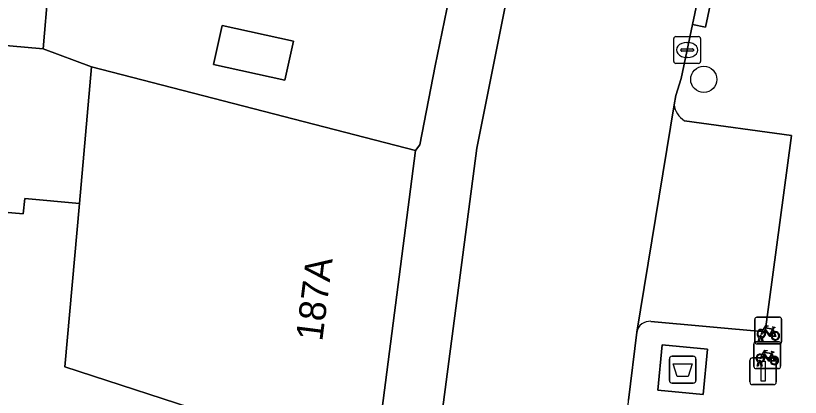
# Model space of a CAD drawing. Extents: x 161248 to 161848, y 384871 to 385383.
# Drawn here: x 161674.85 to 161704.18, y 384990.69 to 385004.94 of the extents above; entities that cross this region are included whole.
import ezdxf

# ---------------------------------------------------------------- set-up
doc = ezdxf.new("R2010")
doc.units = 0
for name, color, linetype in [('IMGEO_Afval_apart_plaats', 7, 'Continuous'), ('IMGEO_Boom', 7, 'Continuous'), ('IMGEO_Erf', 7, 'Continuous'), ('IMGEO_Fietsenrek', 7, 'Continuous'), ('IMGEO_Kolk', 7, 'Continuous'), ('IMGEO_Lichtmast', 7, 'Continuous'), ('IMGEO_Pand', 7, 'Continuous'), ('IMGEO_Pand_nummerreeks', 7, 'Continuous'), ('IMGEO_Parkeervlak_open', 7, 'Continuous'), ('IMGEO_Rijbaan_lokaal_open', 7, 'Continuous'), ('IMGEO_Voetpad_gesloten', 7, 'Continuous'), ('IMGEO_Voetpad_open', 7, 'Continuous')]:
    doc.layers.add(name, color=color, linetype=linetype)

msp = doc.modelspace()

# ---------------------------------------------------------------- linework, layer by layer
at = {"layer": 'IMGEO_Afval_apart_plaats'}
for p, q in [((161699.392, 384992.22), (161700.182, 384992.22)), ((161700.182, 384992.22), (161699.392, 384992.22)), ((161699.292, 384991.32), (161699.292, 384992.12)), ((161699.292, 384992.12), (161699.292, 384991.32)), ((161700.282, 384992.12), (161700.282, 384991.32)), ((161700.282, 384991.32), (161700.282, 384992.12)), ((161700.182, 384991.22), (161699.392, 384991.22)), ((161699.392, 384991.22), (161700.182, 384991.22))]:
    msp.add_line(p, q, dxfattribs=at)
msp.add_lwpolyline([(161699.435, 384991.934), (161700.139, 384991.934), (161699.99, 384991.464), (161699.584, 384991.464), (161699.435, 384991.934)], dxfattribs=at)
for centre, start, end in [((161699.392, 384992.12), 90, 180), ((161699.392, 384992.12), 90, 180), ((161700.182, 384992.12), 0, 90), ((161700.182, 384992.12), 360, 90), ((161699.392, 384991.32), 180, 270), ((161699.392, 384991.32), 180, 270), ((161700.182, 384991.32), 270, 0), ((161700.182, 384991.32), 270, 0)]:
    msp.add_arc(centre, 0.1, start, end, dxfattribs=at)
at = {"layer": 'IMGEO_Boom'}
msp.add_circle((161700.575, 385002.565), 0.489, dxfattribs=at)
at = {"layer": 'IMGEO_Erf'}
for points in [[(161676.071, 385005.916), (161675.876, 385003.712), (161677.685, 385003.029), (161689.793, 384999.91), (161689.963, 385000.114), (161690.54, 385003.076), (161691.142, 385006.05)], [(161687.042, 384959.42), (161687.564, 384974.827), (161681.278, 384975.098), (161680.356, 384975.133), (161680.242, 384972.094), (161674.921, 384972.295), (161675.036, 384975.334), (161676.32, 384975.285), (161676.539, 384981.075), (161681.479, 384980.93), (161682.094, 384980.912), (161682.436, 384989.956), (161676.695, 384991.828), (161677.235, 384997.933), (161675.189, 384998.114), (161675.139, 384997.544), (161670.463, 384997.957)]]:
    msp.add_lwpolyline(points, dxfattribs=at)
msp.add_lwpolyline([(161685.233, 385003.995), (161684.91, 385002.53), (161682.251, 385003.116), (161682.574, 385004.58)], close=True, dxfattribs=at)
at = {"layer": 'IMGEO_Fietsenrek'}
for p, q in [((161702.485, 384992.757), (161702.485, 384993.598)), ((161702.485, 384993.598), (161702.485, 384992.757)), ((161702.56, 384993.682), (161703.401, 384993.682)), ((161703.401, 384993.682), (161702.56, 384993.682)), ((161703.485, 384993.607), (161703.485, 384992.766)), ((161703.485, 384992.766), (161703.485, 384993.607)), ((161703.172, 384993.231), (161703.208, 384993.136)), ((161702.523, 384992.763), (161703.364, 384992.763)), ((161703.364, 384992.763), (161702.523, 384992.763)), ((161702.612, 384992.766), (161702.651, 384992.926)), ((161702.646, 384992.766), (161702.612, 384992.766)), ((161702.681, 384992.914), (161702.646, 384992.766)), ((161702.723, 384992.938), (161702.722, 384992.942)), ((161702.764, 384992.766), (161702.73, 384992.908)), ((161702.754, 384992.949), (161702.755, 384992.942)), ((161702.762, 384992.912), (161702.797, 384992.766)), ((161702.797, 384992.766), (161702.764, 384992.766)), ((161702.448, 384991.838), (161702.448, 384992.679)), ((161702.448, 384992.679), (161702.448, 384991.838)), ((161703.41, 384992.682), (161702.569, 384992.682)), ((161702.569, 384992.682), (161703.41, 384992.682)), ((161703.448, 384992.688), (161703.448, 384991.847)), ((161703.448, 384991.847), (161703.448, 384992.688)), ((161703.135, 384992.312), (161703.171, 384992.217)), ((161702.575, 384991.847), (161702.614, 384992.007)), ((161702.609, 384991.847), (161702.575, 384991.847)), ((161702.644, 384991.995), (161702.609, 384991.847)), ((161702.686, 384992.019), (161702.685, 384992.023)), ((161702.727, 384991.847), (161702.693, 384991.989)), ((161702.717, 384992.03), (161702.718, 384992.023)), ((161702.725, 384991.993), (161702.76, 384991.847)), ((161702.76, 384991.847), (161702.727, 384991.847)), ((161703.373, 384991.763), (161702.532, 384991.763)), ((161702.532, 384991.763), (161703.373, 384991.763))]:
    msp.add_line(p, q, dxfattribs=at)
for points in [[(161702.798, 384993.208), (161702.893, 384993.372), (161702.979, 384993.358), (161702.981, 384993.349), (161702.925, 384993.338), (161702.898, 384993.293), (161703.154, 384993.252)], [(161703.154, 384993.252), (161703.179, 384993.301), (161703.173, 384993.305), (161703.15, 384993.309), (161703.138, 384993.316), (161703.137, 384993.319), (161703.139, 384993.324), (161703.234, 384993.309), (161703.236, 384993.299), (161703.226, 384993.286), (161703.214, 384993.28), (161703.2, 384993.286), (161703.172, 384993.231)], [(161702.819, 384993.156), (161702.767, 384993.066), (161702.727, 384993.041), (161702.728, 384993.088), (161702.783, 384993.182)], [(161703.094, 384992.964), (161703.044, 384992.964), (161702.853, 384993.215), (161702.834, 384993.183)], [(161703.141, 384993.227), (161702.884, 384993.268), (161702.867, 384993.239), (161703.034, 384993.019), (161703.141, 384993.227)], [(161703.189, 384993.129), (161703.159, 384993.206), (161703.05, 384992.988), (161703.093, 384992.988)], [(161703.123, 384992.988), (161703.243, 384992.987), (161703.199, 384993.101)], [(161703.219, 384993.108), (161703.274, 384992.963), (161703.124, 384992.963)], [(161702.761, 384992.289), (161702.856, 384992.453), (161702.942, 384992.439), (161702.944, 384992.43), (161702.888, 384992.419), (161702.861, 384992.374), (161703.117, 384992.333)], [(161702.782, 384992.237), (161702.73, 384992.147), (161702.69, 384992.122), (161702.691, 384992.169), (161702.746, 384992.263)], [(161703.057, 384992.045), (161703.007, 384992.045), (161702.816, 384992.296), (161702.797, 384992.264)], [(161703.104, 384992.308), (161702.847, 384992.349), (161702.83, 384992.32), (161702.997, 384992.1), (161703.104, 384992.308)], [(161703.152, 384992.21), (161703.122, 384992.287), (161703.013, 384992.069), (161703.056, 384992.069)], [(161703.086, 384992.069), (161703.206, 384992.068), (161703.162, 384992.182)], [(161703.182, 384992.189), (161703.237, 384992.044), (161703.087, 384992.044)], [(161703.117, 384992.333), (161703.142, 384992.382), (161703.136, 384992.386), (161703.113, 384992.39), (161703.101, 384992.397), (161703.1, 384992.4), (161703.102, 384992.405), (161703.197, 384992.39), (161703.199, 384992.38), (161703.189, 384992.367), (161703.177, 384992.361), (161703.163, 384992.367), (161703.135, 384992.312)]]:
    msp.add_lwpolyline(points, dxfattribs=at)
for centre, radius, start, end in [((161702.563, 384993.604), 0.0779, 92.4484, 184.2845), ((161702.563, 384993.604), 0.0779, 92.4484, 184.2845), ((161703.407, 384993.604), 0.0779, 2.4484, 94.2845), ((161703.407, 384993.604), 0.0779, 2.4484, 94.2845), ((161702.725, 384993.067), 0.159, 62.6766, 242.1369), ((161702.725, 384993.067), 0.129, 63.3192, 238.903), ((161702.725, 384993.067), 0.129, 283.6043, 43.4302), ((161702.725, 384993.067), 0.159, 283.5766, 46.6042), ((161703.252, 384992.983), 0.159, 113.3408, 178.3217), ((161703.252, 384992.983), 0.159, 187.0065, 105.7708), ((161703.252, 384992.983), 0.129, 113.923, 177.9556), ((161703.252, 384992.983), 0.129, 188.6715, 104.5883), ((161702.526, 384992.685), 0.0779, 92.4484, 184.2845), ((161702.526, 384992.685), 0.0779, 92.4484, 184.2845), ((161702.563, 384992.76), 0.0779, 182.4484, 274.2845), ((161702.563, 384992.76), 0.0779, 182.4484, 274.2845), ((161702.705, 384992.938), 0.0499, 12.8025, 158.6934), ((161702.725, 384993.067), 0.159, 253.9967, 271.7867), ((161702.705, 384992.938), 0.0174, 12.8025, 163.4502), ((161702.725, 384993.067), 0.129, 253.415, 269.0204), ((161703.37, 384992.685), 0.0779, 2.4484, 94.2845), ((161703.37, 384992.685), 0.0779, 2.4484, 94.2845), ((161703.407, 384992.76), 0.0779, 272.4484, 4.2845), ((161703.407, 384992.76), 0.0779, 272.4484, 4.2845), ((161702.688, 384992.148), 0.159, 62.6766, 242.1369), ((161702.688, 384992.148), 0.129, 63.3192, 238.903), ((161702.688, 384992.148), 0.129, 283.6043, 43.4302), ((161702.688, 384992.148), 0.159, 283.5766, 46.6042), ((161703.215, 384992.064), 0.159, 113.3408, 178.3217), ((161703.215, 384992.064), 0.159, 187.0065, 105.7708), ((161703.215, 384992.064), 0.129, 113.923, 177.9556), ((161703.215, 384992.064), 0.129, 188.6715, 104.5883), ((161702.526, 384991.841), 0.0779, 182.4484, 274.2845), ((161702.526, 384991.841), 0.0779, 182.4484, 274.2845), ((161702.668, 384992.019), 0.0499, 12.8025, 158.6934), ((161702.688, 384992.148), 0.159, 253.9967, 271.7867), ((161702.668, 384992.019), 0.0174, 12.8025, 163.4502), ((161702.688, 384992.148), 0.129, 253.415, 269.0204), ((161703.37, 384991.841), 0.0779, 272.4484, 4.2845), ((161703.37, 384991.841), 0.0779, 272.4484, 4.2845)]:
    msp.add_arc(centre, radius, start, end, dxfattribs=at)
at = {"layer": 'IMGEO_Kolk'}
for p, q in [((161699.53, 385004.164), (161700.382, 385004.164)), ((161699.455, 385003.238), (161699.455, 385004.09)), ((161699.943, 385003.944), (161699.968, 385003.944)), ((161700.456, 385004.09), (161700.456, 385003.238)), ((161699.714, 385003.658), (161699.714, 385003.67)), ((161700.152, 385003.621), (161699.754, 385003.621)), ((161699.757, 385003.707), (161700.155, 385003.707)), ((161700.198, 385003.67), (161700.198, 385003.658)), ((161699.966, 385003.384), (161699.941, 385003.384)), ((161700.382, 385003.164), (161699.53, 385003.164))]:
    msp.add_line(p, q, dxfattribs=at)
for points in [[(161699.53, 385004.164), (161700.382, 385004.164)], [(161699.455, 385003.238), (161699.455, 385004.09)], [(161700.456, 385004.09), (161700.456, 385003.238)], [(161700.382, 385003.164), (161699.53, 385003.164)]]:
    msp.add_lwpolyline(points, dxfattribs=at)
for centre, radius, start, end in [((161699.532, 385004.088), 0.0765, 91.552, 178.448), ((161699.532, 385004.088), 0.0765, 91.552, 178.448), ((161700.38, 385004.088), 0.0765, 1.552, 88.448), ((161700.38, 385004.088), 0.0765, 1.552, 88.448), ((161699.754, 385003.667), 0.0403, 85.8775, 175.7526), ((161699.751, 385003.657), 0.0366, 178.938, 274.7102), ((161700.155, 385003.664), 0.043, 264.8664, 352.4533), ((161700.159, 385003.669), 0.0386, 1.7309, 96.639), ((161699.532, 385003.24), 0.0765, 181.552, 268.448), ((161699.532, 385003.24), 0.0765, 181.552, 268.448), ((161700.38, 385003.24), 0.0765, 271.552, 358.448), ((161700.38, 385003.24), 0.0765, 271.552, 358.448)]:
    msp.add_arc(centre, radius, start, end, dxfattribs=at)
for centre, major_axis, ratio, start_param, end_param in [((161699.942, 385003.664), (-0.387, 0.002), 0.722429, 4.712389, 7.853982), ((161699.967, 385003.664), (-0.39, 0.002), 0.717154, 1.570796, 4.712389)]:
    msp.add_ellipse(centre, major_axis=major_axis, ratio=ratio, start_param=start_param, end_param=end_param, dxfattribs=at)
at = {"layer": 'IMGEO_Lichtmast'}
for p, q in [((161702.397, 384992.162), (161703.187, 384992.162)), ((161703.187, 384992.162), (161702.397, 384992.162)), ((161702.297, 384991.262), (161702.297, 384992.062)), ((161702.297, 384992.062), (161702.297, 384991.262)), ((161703.287, 384992.062), (161703.287, 384991.262)), ((161703.287, 384991.262), (161703.287, 384992.062)), ((161703.187, 384991.162), (161702.397, 384991.162)), ((161702.397, 384991.162), (161703.187, 384991.162))]:
    msp.add_line(p, q, dxfattribs=at)
msp.add_lwpolyline([(161702.717, 384992.037), (161702.867, 384992.037), (161702.867, 384991.287), (161702.717, 384991.287), (161702.717, 384992.037)], dxfattribs=at)
for centre, start, end in [((161702.397, 384992.062), 90, 180), ((161702.397, 384992.062), 90, 180), ((161703.187, 384992.062), 0, 90), ((161703.187, 384992.062), 360, 90), ((161702.397, 384991.262), 180, 270), ((161702.397, 384991.262), 180, 270), ((161703.187, 384991.262), 270, 0), ((161703.187, 384991.262), 270, 0)]:
    msp.add_arc(centre, 0.1, start, end, dxfattribs=at)
at = {"layer": 'IMGEO_Pand'}
for points in [[(161662.725, 385004.875), (161675.876, 385003.712), (161676.071, 385005.916), (161671.449, 385006.324), (161671.636, 385008.437), (161663.106, 385009.192)], [(161677.685, 385003.029), (161675.876, 385003.712), (161662.725, 385004.875), (161662.325, 385000.349), (161666.274, 385000), (161670.61, 384999.617), (161670.463, 384997.957), (161675.139, 384997.544), (161675.189, 384998.114), (161677.235, 384997.933)], [(161685.233, 385003.995), (161682.574, 385004.58), (161682.251, 385003.116), (161684.91, 385002.53)], [(161689.793, 384999.91), (161677.685, 385003.029), (161677.235, 384997.933), (161676.695, 384991.828), (161682.436, 384989.956), (161684.375, 384989.324), (161688.399, 384989.129)]]:
    msp.add_lwpolyline(points, close=True, dxfattribs=at)
at = {"layer": 'IMGEO_Parkeervlak_open'}
for points in [[(161699.463, 385001.62), (161698.067, 384993.125)], [(161698.602, 384993.527), (161702.865, 384993.13), (161703.854, 385000.464), (161699.849, 385001.02)]]:
    msp.add_lwpolyline(points, dxfattribs=at)
for centre, radius, start, end in [((161700.35, 385001.767), 0.899, 189.3822, 236.1269), ((161698.56, 384993.026), 0.503, 85.2024, 168.6401)]:
    msp.add_arc(centre, radius, start, end, dxfattribs=at)
at = {"layer": 'IMGEO_Rijbaan_lokaal_open'}
for points in [[(161695.406, 384939.447), (161697.013, 384979.259), (161697.592, 384987.605), (161697.757, 384990.585), (161698.067, 384993.125), (161699.463, 385001.62), (161699.529, 385001.962), (161699.731, 385002.596), (161700.158, 385004.616), (161701.87, 385012.717)], [(161693.319, 385006.112), (161692.093, 385000), (161690.685, 384989.277), (161690.556, 384987.296), (161690.544, 384987.105), (161690.086, 384980.097), (161690.073, 384979.9), (161690.016, 384979.024), (161689.843, 384975.29), (161689.648, 384970.041), (161689.25, 384958.941), (161689.115, 384955.181), (161689.098, 384954.71), (161689.064, 384954.249), (161688.958, 384953.539), (161688.789, 384952.843), (161688.558, 384952.163), (161688.268, 384951.508), (161687.921, 384950.88), (161687.518, 384950.287), (161687.065, 384949.731), (161686.563, 384949.219)]]:
    msp.add_lwpolyline(points, dxfattribs=at)
at = {"layer": 'IMGEO_Voetpad_gesloten'}
msp.add_lwpolyline([(161700.714, 384992.484), (161699.022, 384992.646), (161698.86, 384990.956), (161700.552, 384990.794)], close=True, dxfattribs=at)
at = {"layer": 'IMGEO_Voetpad_open'}
for points in [[(161705.595, 385030.288), (161704.227, 385023.875), (161702.148, 385014.035), (161702.637, 385013.932), (161702.361, 385012.627), (161700.646, 385004.513), (161700.158, 385004.616), (161699.731, 385002.596), (161699.529, 385001.962), (161699.463, 385001.62)], [(161691.142, 385006.05), (161690.54, 385003.076), (161689.963, 385000.114), (161689.793, 384999.91), (161688.399, 384989.129), (161688.267, 384987.18), (161689.036, 384987.155), (161690.544, 384987.105), (161690.556, 384987.296), (161690.685, 384989.277), (161692.093, 385000), (161693.319, 385006.112)], [(161699.849, 385001.02), (161703.854, 385000.464), (161702.865, 384993.13), (161698.602, 384993.527)], [(161698.067, 384993.125), (161697.757, 384990.585)]]:
    msp.add_lwpolyline(points, dxfattribs=at)
for points in [[(161700.158, 385004.616), (161700.646, 385004.513), (161702.361, 385012.627), (161702.637, 385013.932), (161702.148, 385014.035), (161701.87, 385012.717)], [(161698.86, 384990.956), (161699.022, 384992.646), (161700.714, 384992.484), (161700.552, 384990.794)]]:
    msp.add_lwpolyline(points, close=True, dxfattribs=at)
for centre, radius, start, end in [((161700.35, 385001.767), 0.899, 189.3822, 236.1269), ((161698.56, 384993.026), 0.503, 85.2024, 168.6401)]:
    msp.add_arc(centre, radius, start, end, dxfattribs=at)

# ---------------------------------------------------------------- texts
at = {"layer": 'IMGEO_Pand_nummerreeks'}
msp.add_text('187A', height=1, rotation=82.7867, dxfattribs=at).set_placement((161686.312, 384992.757))

doc.saveas('drawing.dxf')
